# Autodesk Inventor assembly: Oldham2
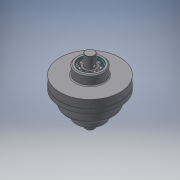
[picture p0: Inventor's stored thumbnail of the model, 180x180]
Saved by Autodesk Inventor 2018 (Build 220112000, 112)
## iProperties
Created: 2021-01
Part Number: Oldham2
Document SubType Name: Assembly
Designer: Janez
Mass: 902.905 g
Surface Area: 2115.46 cm^2
Volume: 603.108 cm^3
Density: 1.49709 g/cm^3
Author: Janez
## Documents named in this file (12)
- C:\Projekti\Standardni elementi\Sklopke\Oldham2.iam
- C:\Projekti\Standardni elementi\Sklopke\zobnikobroč11_1OS.ipt
- C:\Projekti\Standardni elementi\Sklopke\zobnik100-1,5OS.ipt
- C:\Users\Janez\Documents\Inventor\Content Center Files\R2018\en-US\DIN BEARING(1)\DIN 625 SKF - SKF 61806.ipt
- C:\Projekti\Standardni elementi\Sklopke\gred1.ipt
- C:\Projekti\Standardni elementi\Sklopke\Oldham_križna plošča1.ipt
- C:\Projekti\Standardni elementi\Sklopke\obroč za nz.ipt
- C:\Projekti\Standardni elementi\Sklopke\OHdrugi del.ipt
- C:\Users\Janez\Documents\Inventor\Content Center Files\R2018\en-US\DIN 628 SKF(5)\DIN 628 SKF - SKF E2.3204 A-2Z.ipt
- C:\Projekti\Standardni elementi\Sklopke\oldhamsorednja plošča.ipt
- C:\Users\Janez\Documents\Inventor\Content Center Files\R2018\en-US\DIN 472(2)\DIN 472 - 47x1,75.ipt
- C:\Projekti\Standardni elementi\Sklopke\Oldham2\Design Accelerator\Bolted Connection2.iam
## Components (18 placed, 11 different names)
1. zobnikobroč11_1OS:1 — Mate:8, Insert:10
2. DIN 625 SKF SKF 61806:1 — Insert:3, Insert:5
3. DIN 628 SKF- with shields - 32..A-2Z, 33..A-2Z, E2..-2Z SKF E2.3204 A-2Z:1
4. zobnik100-1,5OS:1 — Insert:3, Mate:1, Mate:2, Rotation:1, Mate:9
5. gred1:1 — Insert:5, Mate:3, Mate:4, Mate:7, Rotation:1, Angle:1, Angle:2
6. Oldham_križna plošča1:1 — Mate:1, Mate:2, Mate:5, Mate:6
7. obroč za nz:1 — Mate:4, Mate:8, Insert:10, Mate:9, Flush:2
8. OHdrugi del:1 — Mate:5, Mate:6, Mate:7, Insert:13
9. oldhamsorednja plošča:1 — Mate:12, Flush:2, Insert:15, Mate:13
10. DIN 628 SKF- with shields - 32..A-2Z, 33..A-2Z, E2..-2Z SKF E2.3204 A-2Z:2 — Insert:13
11. DIN 472 47x1,75:1
12. DIN 472 47x1,75:2 — Insert:15
13. Bolted Connection:1 [sub-assembly] — Mate:13, Mate:14
14. Bolted Connection:2 [sub-assembly]
15. Bolted Connection:3 [sub-assembly]
16. Bolted Connection:4 [sub-assembly]
17. Bolted Connection:5 [sub-assembly]
18. Bolted Connection:6 [sub-assembly]
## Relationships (21: Mate 12, Insert 5, Angle 2, RelateRotation 1, Flush 1)
- Insert:3: DIN 625 SKF SKF 61806:1 ↔ zobnik100-1,5OS:1
- Mate:1: zobnik100-1,5OS:1 ↔ Oldham_križna plošča1:1
- Mate:2: zobnik100-1,5OS:1 ↔ Oldham_križna plošča1:1
- Insert:5: DIN 625 SKF SKF 61806:1 ↔ gred1:1
- Mate:3: gred1:1
- Mate:4: gred1:1 ↔ obroč za nz:1
- Mate:5: Oldham_križna plošča1:1 ↔ OHdrugi del:1
- Mate:6: Oldham_križna plošča1:1 ↔ OHdrugi del:1
- Mate:7: gred1:1 ↔ OHdrugi del:1
- Rotation:1 [RelateRotation]: zobnik100-1,5OS:1 ↔ gred1:1
- Mate:8: zobnikobroč11_1OS:1 ↔ obroč za nz:1
- Insert:10: zobnikobroč11_1OS:1 ↔ obroč za nz:1
- Mate:9: zobnik100-1,5OS:1 ↔ obroč za nz:1
- Insert:13: OHdrugi del:1 ↔ DIN 628 SKF- with shields - 32..A-2Z, 33..A-2Z, E2..-2Z SKF E2.3204 A-2Z:2
- Mate:12: oldhamsorednja plošča:1
- Flush:2: obroč za nz:1 ↔ oldhamsorednja plošča:1
- Insert:15: oldhamsorednja plošča:1 ↔ DIN 472 47x1,75:2
- Angle:2: gred1:1
- Mate:13: oldhamsorednja plošča:1 ↔ Bolted Connection:1
- Mate:14: Bolted Connection:1
- Angle:1: gred1:1
